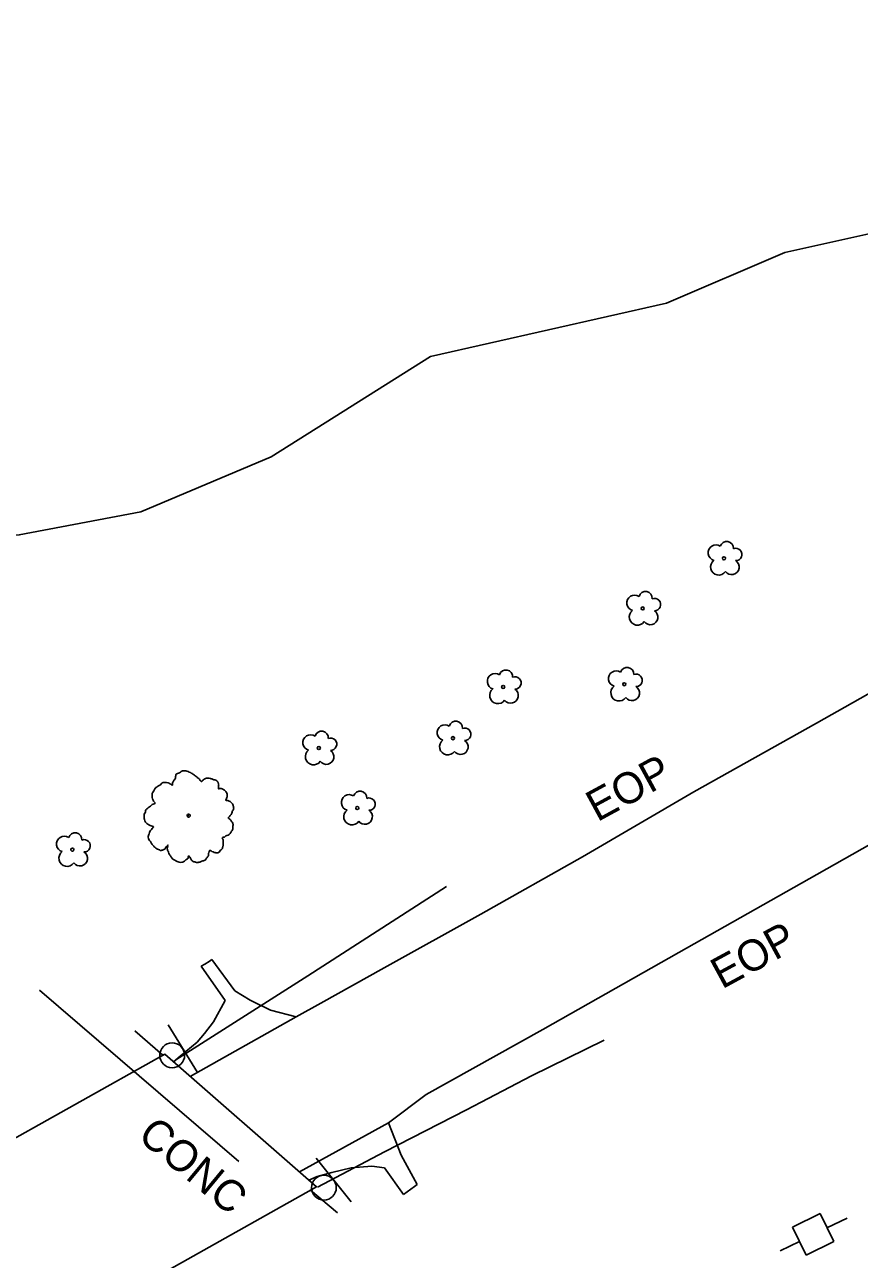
# Model space of a CAD drawing. Extents: x 2076109 to 2080761, y 592812 to 596750.
# Drawn here: x 2077392.1 to 2077526.3, y 595822.6 to 596021.2 of the extents above; entities that cross this region are included whole.
import ezdxf

# ---------------------------------------------------------------- set-up
doc = ezdxf.new("R2010")
doc.units = 0
for name, color, linetype in [('Default', 7, 'Continuous'), ('RD_EX_BldgApp', 7, 'Continuous'), ('RD_EX_Bridge', 7, 'Continuous'), ('RD_EX_Bridge_txCode', 7, 'Continuous'), ('RD_EX_Conc', 7, 'Continuous'), ('RD_EX_GuardRail', 7, 'Continuous'), ('RD_EX_Road', 7, 'Continuous'), ('RD_EX_Road_txCode', 7, 'Continuous'), ('RD_EX_UT', 7, 'Continuous'), ('RD_EX_VEG', 7, 'Continuous'), ('RD_Sketch1', 7, 'Continuous')]:
    doc.layers.add(name, color=color, linetype=linetype)

msp = doc.modelspace()

# ---------------------------------------------------------------- linework, layer by layer
at = {"layer": 'Default'}
msp.add_arc((2035586.7, 547847.96), 63546.51, 48.5011873, 49.2923126, dxfattribs=at)
msp.add_arc((2035586.7, 547847.96), 63546.51, 48.5011873, 49.2923126, dxfattribs=at)
at = {"layer": 'RD_EX_BldgApp'}
for p, q in [((2077419.87, 595852.63), (2077415.15, 595860.29)), ((2077419.87, 595852.63), (2077415.15, 595860.29)), ((2077444.58, 595831.87), (2077438.95, 595838.88)), ((2077444.58, 595831.87), (2077438.95, 595838.88))]:
    msp.add_line(p, q, dxfattribs=at)
for centre in [(2077415.78, 595855.41), (2077415.78, 595855.41), (2077440.18, 595834.12), (2077440.18, 595834.12)]:
    msp.add_circle(centre, 2, dxfattribs=at)
at = {"layer": 'RD_EX_Bridge'}
for p, q in [((2077409.76, 595859.33), (2077414.27, 595855.42)), ((2077409.76, 595859.33), (2077414.27, 595855.42)), ((2077442.36, 595830.09), (2077438.01, 595833.71)), ((2077442.36, 595830.09), (2077438.01, 595833.71))]:
    msp.add_line(p, q, dxfattribs=at)
msp.add_lwpolyline([(2077182.69, 595725.56), (2077226.26, 595749.95), (2077278.63, 595779.43), (2077318.69, 595801.87), (2077370.98, 595831.15), (2077414.59, 595855.59), (2077438.98, 595834.26), (2077395.4, 595809.74), (2077342.89, 595780.4), (2077302.73, 595757.84), (2077250.38, 595728.31), (2077206.95, 595704.06)], close=True, dxfattribs=at)
msp.add_lwpolyline([(2077182.69, 595725.56), (2077226.26, 595749.95), (2077278.63, 595779.43), (2077318.69, 595801.87), (2077370.98, 595831.15), (2077414.59, 595855.59), (2077438.98, 595834.26), (2077395.4, 595809.74), (2077342.89, 595780.4), (2077302.73, 595757.84), (2077250.38, 595728.31), (2077206.95, 595704.06)], close=True, dxfattribs=at)
at = {"layer": 'RD_EX_Conc'}
for p, q in [((2077424.3, 595864.22), (2077420.43, 595869.75)), ((2077424.3, 595864.22), (2077420.43, 595869.75)), ((2077449.95, 595837.32), (2077452.97, 595833.04)), ((2077449.95, 595837.32), (2077452.97, 595833.04))]:
    msp.add_line(p, q, dxfattribs=at)
for points in [[(2077420.43, 595869.75), (2077421.01, 595870.08), (2077421.72, 595870.52), (2077422.18, 595870.8)], [(2077420.43, 595869.75), (2077421.01, 595870.08), (2077421.72, 595870.52), (2077422.18, 595870.8)], [(2077422.18, 595870.8), (2077425.85, 595865.79), (2077428.32, 595864.3), (2077431.62, 595862.65), (2077435.74, 595861.59)], [(2077422.18, 595870.8), (2077425.85, 595865.79), (2077428.32, 595864.3), (2077431.62, 595862.65), (2077435.74, 595861.59)], [(2077416, 595854.36), (2077417.08, 595855.26), (2077419.78, 595857.52), (2077420.98, 595858.94), (2077422.44, 595860.78), (2077424.3, 595864.22)], [(2077416, 595854.36), (2077417.08, 595855.26), (2077419.78, 595857.52), (2077420.98, 595858.94), (2077422.44, 595860.78), (2077424.3, 595864.22)], [(2077424.3, 595864.22), (2077424.3, 595864.22)], [(2077424.3, 595864.22), (2077424.3, 595864.22)], [(2077455.21, 595834.64), (2077452.61, 595839.34), (2077450.57, 595844.56)], [(2077455.21, 595834.64), (2077452.61, 595839.34), (2077450.57, 595844.56)], [(2077437.74, 595835.34), (2077439.09, 595835.94), (2077441.48, 595836.54), (2077444.58, 595837.32), (2077447.89, 595837.59), (2077449.95, 595837.32)], [(2077437.74, 595835.34), (2077439.09, 595835.94), (2077441.48, 595836.54), (2077444.58, 595837.32), (2077447.89, 595837.59), (2077449.95, 595837.32)], [(2077452.97, 595833.04), (2077453.56, 595833.45), (2077454.77, 595834.33), (2077455.21, 595834.64)], [(2077452.97, 595833.04), (2077453.56, 595833.45), (2077454.77, 595834.33), (2077455.21, 595834.64)]]:
    msp.add_lwpolyline(points, dxfattribs=at)
at = {"layer": 'RD_EX_GuardRail'}
for points in [[(2077459.93, 595882.54), (2077437.6, 595868.21), (2077416.38, 595854.69)], [(2077459.93, 595882.54), (2077437.6, 595868.21), (2077416.38, 595854.69)], [(2077439.13, 595834.18), (2077449.93, 595839.88), (2077463.1, 595846.65), (2077473.58, 595852.13), (2077485.27, 595857.86)], [(2077439.13, 595834.18), (2077449.93, 595839.88), (2077463.1, 595846.65), (2077473.58, 595852.13), (2077485.27, 595857.86)]]:
    msp.add_lwpolyline(points, dxfattribs=at)
at = {"layer": 'RD_EX_Road'}
for points in [[(2077543.8, 595922.59), (2077519.41, 595908.81), (2077499.67, 595897.76), (2077481.77, 595887.31), (2077465.41, 595878.13), (2077449.9, 595869.47), (2077439.7, 595863.82)], [(2077543.8, 595922.59), (2077519.41, 595908.81), (2077499.67, 595897.76), (2077481.77, 595887.31), (2077465.41, 595878.13), (2077449.9, 595869.47), (2077439.7, 595863.82)], [(2077456.64, 595849.12), (2077475.41, 595859.57), (2077497.28, 595871.94), (2077518.22, 595883.81), (2077537.74, 595894.82)], [(2077456.64, 595849.12), (2077475.41, 595859.57), (2077497.28, 595871.94), (2077518.22, 595883.81), (2077537.74, 595894.82)], [(2077439.7, 595863.82), (2077435.74, 595861.59), (2077418.7, 595852)], [(2077439.7, 595863.82), (2077435.74, 595861.59), (2077418.7, 595852)], [(2077436.25, 595836.65), (2077450.57, 595844.56), (2077456.64, 595849.12)], [(2077436.25, 595836.65), (2077450.57, 595844.56), (2077456.64, 595849.12)]]:
    msp.add_lwpolyline(points, dxfattribs=at)
at = {"layer": 'RD_EX_UT'}
for p, q in [((2077520.02, 595829.97), (2077515.53, 595827.77)), ((2077520.02, 595829.97), (2077515.53, 595827.77)), ((2077522.22, 595825.48), (2077520.02, 595829.97)), ((2077522.22, 595825.48), (2077520.02, 595829.97)), ((2077521.08, 595827.64), (2077524.35, 595829.24)), ((2077521.08, 595827.64), (2077524.35, 595829.24)), ((2077515.53, 595827.77), (2077517.73, 595823.28)), ((2077515.53, 595827.77), (2077517.73, 595823.28)), ((2077513.57, 595823.96), (2077516.69, 595825.49)), ((2077513.57, 595823.96), (2077516.69, 595825.49)), ((2077517.73, 595823.28), (2077522.22, 595825.48)), ((2077517.73, 595823.28), (2077522.22, 595825.48))]:
    msp.add_line(p, q, dxfattribs=at)
at = {"layer": 'RD_EX_VEG'}
for points in [[(2077452.32, 596036.38), (2077484.3, 596038.76), (2077519.05, 596039.86), (2077543.06, 596044.55), (2077554.7, 596042.23), (2077566.69, 596033.37), (2077573.01, 596026.73), (2077575.87, 596012.73), (2077573.1, 596007.72), (2077559.2, 595996.51), (2077543.73, 595991.04), (2077514.3, 595984.51), (2077495.27, 595976.35), (2077457.35, 595967.82), (2077431.71, 595951.64)], [(2077452.32, 596036.38), (2077484.3, 596038.76), (2077519.05, 596039.86), (2077543.06, 596044.55), (2077554.7, 596042.23), (2077566.69, 596033.37), (2077573.01, 596026.73), (2077575.87, 596012.73), (2077573.1, 596007.72), (2077559.2, 595996.51), (2077543.73, 595991.04), (2077514.3, 595984.51), (2077495.27, 595976.35), (2077457.35, 595967.82), (2077431.71, 595951.64)], [(2077431.71, 595951.64), (2077410.74, 595942.79), (2077391.2, 595939.11), (2077374.98, 595938.69), (2077362.23, 595941.05), (2077351, 595938.05), (2077345.02, 595933.18), (2077341.51, 595928.41), (2077336.03, 595916.1), (2077330.47, 595912.16), (2077323.87, 595911.13), (2077317.15, 595914.07), (2077296.95, 595933.28), (2077273.45, 595955.1)], [(2077431.71, 595951.64), (2077410.74, 595942.79), (2077391.2, 595939.11), (2077374.98, 595938.69), (2077362.23, 595941.05), (2077351, 595938.05), (2077345.02, 595933.18), (2077341.51, 595928.41), (2077336.03, 595916.1), (2077330.47, 595912.16), (2077323.87, 595911.13), (2077317.15, 595914.07), (2077296.95, 595933.28), (2077273.45, 595955.1)]]:
    msp.add_lwpolyline(points, dxfattribs=at)
for centre, radius in [((2077504.53, 595935.34), 0.25), ((2077504.53, 595935.34), 0.25), ((2077491.46, 595927.28), 0.25), ((2077491.46, 595927.28), 0.25), ((2077469.02, 595914.66), 0.25), ((2077469.02, 595914.66), 0.25), ((2077488.49, 595915.09), 0.25), ((2077488.49, 595915.09), 0.25), ((2077460.94, 595906.42), 0.25), ((2077460.94, 595906.42), 0.25), ((2077439.37, 595904.82), 0.25), ((2077439.37, 595904.82), 0.25), ((2077418.43, 595893.96), 0.25), ((2077418.43, 595893.96), 0.25), ((2077418.41, 595893.95), 0.0001), ((2077418.41, 595893.95), 0.0001), ((2077445.55, 595895.18), 0.25), ((2077445.55, 595895.18), 0.25), ((2077399.73, 595888.49), 0.25), ((2077399.73, 595888.49), 0.25)]:
    msp.add_circle(centre, radius, dxfattribs=at)
for centre, radius, start, end in [((2077504.98, 595936.98), 1.08, 354.7355, 164.5153), ((2077504.98, 595936.98), 1.08, 354.7355, 164.5153), ((2077503.24, 595936.23), 1.26, 56.211, 254.4932), ((2077503.24, 595936.23), 1.26, 56.211, 254.4932), ((2077506.43, 595935.96), 0.995, 268.5218, 111.806), ((2077506.43, 595935.96), 0.995, 268.5218, 111.806), ((2077503.69, 595933.96), 1.32, 126.6419, 325.5182), ((2077503.69, 595933.96), 1.32, 126.6419, 325.5182), ((2077505.75, 595933.94), 1.22, 216.3259, 57.8639), ((2077505.75, 595933.94), 1.22, 216.3259, 57.8639), ((2077491.91, 595928.93), 1.08, 354.7355, 164.5153), ((2077491.91, 595928.93), 1.08, 354.7355, 164.5153), ((2077490.17, 595928.17), 1.26, 56.211, 254.4932), ((2077490.17, 595928.17), 1.26, 56.211, 254.4932), ((2077493.36, 595927.9), 0.995, 268.5218, 111.806), ((2077493.36, 595927.9), 0.995, 268.5218, 111.806), ((2077490.62, 595925.9), 1.32, 126.6419, 325.5182), ((2077490.62, 595925.9), 1.32, 126.6419, 325.5182), ((2077492.69, 595925.88), 1.22, 216.3259, 57.8639), ((2077492.69, 595925.88), 1.22, 216.3259, 57.8639), ((2077488.94, 595916.73), 1.08, 354.7355, 164.5153), ((2077488.94, 595916.73), 1.08, 354.7355, 164.5153), ((2077467.72, 595915.55), 1.26, 56.211, 254.4932), ((2077467.72, 595915.55), 1.26, 56.211, 254.4932), ((2077469.46, 595916.31), 1.08, 354.7355, 164.5153), ((2077469.46, 595916.31), 1.08, 354.7355, 164.5153), ((2077470.91, 595915.28), 0.995, 268.5218, 111.806), ((2077470.91, 595915.28), 0.995, 268.5218, 111.806), ((2077487.2, 595915.98), 1.26, 56.211, 254.4932), ((2077487.2, 595915.98), 1.26, 56.211, 254.4932), ((2077490.39, 595915.71), 0.995, 268.5218, 111.806), ((2077490.39, 595915.71), 0.995, 268.5218, 111.806), ((2077468.17, 595913.28), 1.32, 126.6419, 325.5182), ((2077468.17, 595913.28), 1.32, 126.6419, 325.5182), ((2077470.24, 595913.26), 1.22, 216.3259, 57.8639), ((2077470.24, 595913.26), 1.22, 216.3259, 57.8639), ((2077487.65, 595913.71), 1.32, 126.6419, 325.5182), ((2077487.65, 595913.71), 1.32, 126.6419, 325.5182), ((2077489.72, 595913.68), 1.22, 216.3259, 57.8639), ((2077489.72, 595913.68), 1.22, 216.3259, 57.8639), ((2077459.65, 595907.31), 1.26, 56.211, 254.4932), ((2077459.65, 595907.31), 1.26, 56.211, 254.4932), ((2077461.39, 595908.07), 1.08, 354.7355, 164.5153), ((2077461.39, 595908.07), 1.08, 354.7355, 164.5153), ((2077462.84, 595907.04), 0.995, 268.5218, 111.806), ((2077462.84, 595907.04), 0.995, 268.5218, 111.806), ((2077438.07, 595905.71), 1.26, 56.211, 254.4932), ((2077438.07, 595905.71), 1.26, 56.211, 254.4932), ((2077439.82, 595906.47), 1.08, 354.7355, 164.5153), ((2077439.82, 595906.47), 1.08, 354.7355, 164.5153), ((2077441.27, 595905.45), 0.995, 268.5218, 111.806), ((2077441.27, 595905.45), 0.995, 268.5218, 111.806), ((2077460.1, 595905.04), 1.32, 126.6419, 325.5182), ((2077460.1, 595905.04), 1.32, 126.6419, 325.5182), ((2077462.16, 595905.02), 1.22, 216.3259, 57.8639), ((2077462.16, 595905.02), 1.22, 216.3259, 57.8639), ((2077438.52, 595903.45), 1.32, 126.6419, 325.5182), ((2077438.52, 595903.45), 1.32, 126.6419, 325.5182), ((2077440.59, 595903.42), 1.22, 216.3259, 57.8639), ((2077440.59, 595903.42), 1.22, 216.3259, 57.8639), ((2077446, 595896.83), 1.08, 354.7355, 164.5153), ((2077446, 595896.83), 1.08, 354.7355, 164.5153), ((2077444.25, 595896.07), 1.26, 56.211, 254.4932), ((2077444.25, 595896.07), 1.26, 56.211, 254.4932), ((2077447.44, 595895.81), 0.995, 268.5218, 111.806), ((2077447.44, 595895.81), 0.995, 268.5218, 111.806), ((2077444.7, 595893.8), 1.32, 126.6419, 325.5182), ((2077444.7, 595893.8), 1.32, 126.6419, 325.5182), ((2077446.77, 595893.78), 1.22, 216.3259, 57.8639), ((2077446.77, 595893.78), 1.22, 216.3259, 57.8639), ((2077398.44, 595889.38), 1.26, 56.0792, 254.3614), ((2077398.44, 595889.38), 1.26, 56.0792, 254.3614), ((2077400.18, 595890.13), 1.08, 354.6037, 164.3834), ((2077400.18, 595890.13), 1.08, 354.6037, 164.3834), ((2077401.63, 595889.11), 0.995, 268.39, 111.6741), ((2077401.63, 595889.11), 0.995, 268.39, 111.6741), ((2077398.88, 595887.11), 1.32, 126.51, 325.3863), ((2077398.88, 595887.11), 1.32, 126.51, 325.3863), ((2077400.95, 595887.08), 1.22, 216.1941, 57.732), ((2077400.95, 595887.08), 1.22, 216.1941, 57.732)]:
    msp.add_arc(centre, radius, start, end, dxfattribs=at)
for points in [[(2077423.16, 595899.34), (2077422.95, 595899.56), (2077422.64, 595899.69), (2077422.38, 595899.77), (2077422.16, 595899.86), (2077421.93, 595899.93), (2077421.58, 595899.99), (2077421.28, 595899.98), (2077421.03, 595899.87), (2077420.84, 595899.73), (2077420.63, 595899.56), (2077420.51, 595899.42), (2077420.4, 595899.49), (2077420.3, 595899.6), (2077420.16, 595899.82), (2077419.97, 595899.98), (2077419.78, 595900.14), (2077419.5, 595900.35), (2077419.23, 595900.58), (2077418.99, 595900.72), (2077418.71, 595900.89), (2077418.34, 595901.03), (2077417.99, 595901.16), (2077417.6, 595901.17), (2077417.11, 595900.97), (2077416.78, 595900.78), (2077416.51, 595900.69), (2077416.33, 595900.25), (2077416.24, 595899.87), (2077416.13, 595899.7), (2077415.91, 595899.32), (2077415.84, 595899.09), (2077415.81, 595898.85), (2077415.74, 595898.88), (2077415.42, 595899.09), (2077415.12, 595899.21), (2077414.65, 595899.31), (2077414.34, 595899.28), (2077414.05, 595899.1), (2077413.81, 595898.85), (2077413.6, 595898.76), (2077413.37, 595898.6), (2077413.3, 595898.56), (2077413.05, 595898.34), (2077412.84, 595897.93), (2077412.63, 595897.65), (2077412.58, 595897.4), (2077412.58, 595897.17), (2077412.55, 595896.86), (2077412.71, 595896.43), (2077412.9, 595896.15), (2077413.03, 595896), (2077412.58, 595895.73), (2077412.31, 595895.5), (2077411.96, 595895.27), (2077411.91, 595895.21), (2077411.57, 595894.88), (2077411.47, 595894.54), (2077411.28, 595894.21), (2077411.27, 595893.92), (2077411.29, 595893.51), (2077411.39, 595893.13), (2077411.69, 595892.71), (2077412.01, 595892.47), (2077412.57, 595892.24), (2077412.8, 595892.13), (2077412.67, 595892.02), (2077412.45, 595891.71), (2077412.18, 595891.39), (2077412.08, 595891.04), (2077411.98, 595890.77), (2077411.93, 595890.48), (2077412.03, 595890.1), (2077412.29, 595889.79), (2077412.52, 595889.4), (2077412.81, 595889.05), (2077413.18, 595888.71), (2077413.73, 595888.43), (2077414.02, 595888.35), (2077414.21, 595888.42), (2077414.61, 595888.58), (2077414.72, 595888.78), (2077415.12, 595889.22), (2077415.08, 595889.02), (2077414.99, 595888.64), (2077415.18, 595888.09), (2077415.37, 595887.7), (2077415.64, 595887.28), (2077415.82, 595887.03), (2077416.23, 595886.78), (2077416.56, 595886.59), (2077416.93, 595886.45), (2077417.34, 595886.46), (2077417.65, 595886.56), (2077417.86, 595886.74), (2077418.16, 595886.98), (2077418.31, 595887.08)], [(2077423.16, 595899.34), (2077422.95, 595899.56), (2077422.64, 595899.69), (2077422.38, 595899.77), (2077422.16, 595899.86), (2077421.93, 595899.93), (2077421.58, 595899.99), (2077421.28, 595899.98), (2077421.03, 595899.87), (2077420.84, 595899.73), (2077420.63, 595899.56), (2077420.51, 595899.42), (2077420.4, 595899.49), (2077420.3, 595899.6), (2077420.16, 595899.82), (2077419.97, 595899.98), (2077419.78, 595900.14), (2077419.5, 595900.35), (2077419.23, 595900.58), (2077418.99, 595900.72), (2077418.71, 595900.89), (2077418.34, 595901.03), (2077417.99, 595901.16), (2077417.6, 595901.17), (2077417.11, 595900.97), (2077416.78, 595900.78), (2077416.51, 595900.69), (2077416.33, 595900.25), (2077416.24, 595899.87), (2077416.13, 595899.7), (2077415.91, 595899.32), (2077415.84, 595899.09), (2077415.81, 595898.85), (2077415.74, 595898.88), (2077415.42, 595899.09), (2077415.12, 595899.21), (2077414.65, 595899.31), (2077414.34, 595899.28), (2077414.05, 595899.1), (2077413.81, 595898.85), (2077413.6, 595898.76), (2077413.37, 595898.6), (2077413.3, 595898.56), (2077413.05, 595898.34), (2077412.84, 595897.93), (2077412.63, 595897.65), (2077412.58, 595897.4), (2077412.58, 595897.17), (2077412.55, 595896.86), (2077412.71, 595896.43), (2077412.9, 595896.15), (2077413.03, 595896), (2077412.58, 595895.73), (2077412.31, 595895.5), (2077411.96, 595895.27), (2077411.91, 595895.21), (2077411.57, 595894.88), (2077411.47, 595894.54), (2077411.28, 595894.21), (2077411.27, 595893.92), (2077411.29, 595893.51), (2077411.39, 595893.13), (2077411.69, 595892.71), (2077412.01, 595892.47), (2077412.57, 595892.24), (2077412.8, 595892.13), (2077412.67, 595892.02), (2077412.45, 595891.71), (2077412.18, 595891.39), (2077412.08, 595891.04), (2077411.98, 595890.77), (2077411.93, 595890.48), (2077412.03, 595890.1), (2077412.29, 595889.79), (2077412.52, 595889.4), (2077412.81, 595889.05), (2077413.18, 595888.71), (2077413.73, 595888.43), (2077414.02, 595888.35), (2077414.21, 595888.42), (2077414.61, 595888.58), (2077414.72, 595888.78), (2077415.12, 595889.22), (2077415.08, 595889.02), (2077414.99, 595888.64), (2077415.18, 595888.09), (2077415.37, 595887.7), (2077415.64, 595887.28), (2077415.82, 595887.03), (2077416.23, 595886.78), (2077416.56, 595886.59), (2077416.93, 595886.45), (2077417.34, 595886.46), (2077417.65, 595886.56), (2077417.86, 595886.74), (2077418.16, 595886.98), (2077418.31, 595887.08)], [(2077418.31, 595887.08), (2077418.37, 595887.26), (2077418.49, 595887.48), (2077418.53, 595887.41), (2077418.64, 595887.26), (2077418.77, 595886.99), (2077418.89, 595886.79), (2077419.15, 595886.6), (2077419.43, 595886.5), (2077419.95, 595886.42), (2077420.46, 595886.6), (2077420.93, 595886.73), (2077421.2, 595886.93), (2077421.31, 595887.13), (2077421.61, 595887.53), (2077421.62, 595887.85), (2077421.66, 595887.98), (2077421.84, 595888.35), (2077421.93, 595888.34), (2077422.18, 595888.2), (2077422.54, 595888.05), (2077422.83, 595887.97), (2077423.12, 595887.96), (2077423.32, 595888.08), (2077423.56, 595888.4), (2077423.86, 595888.67), (2077423.9, 595888.84), (2077423.92, 595889.02), (2077423.99, 595889.22), (2077423.97, 595889.43), (2077423.99, 595889.61), (2077423.98, 595889.75), (2077423.98, 595889.94), (2077423.93, 595890.15), (2077423.85, 595890.29), (2077423.9, 595890.43), (2077424.15, 595890.49), (2077424.25, 595890.53), (2077424.41, 595890.69), (2077424.81, 595890.81), (2077425.11, 595891.08), (2077425.35, 595891.44), (2077425.48, 595891.68), (2077425.55, 595891.99), (2077425.56, 595892.31), (2077425.57, 595892.52), (2077425.52, 595892.73), (2077425.35, 595893.04), (2077425.2, 595893.24), (2077424.93, 595893.46), (2077424.81, 595893.63), (2077424.86, 595893.65), (2077424.96, 595893.77), (2077425.13, 595893.98), (2077425.37, 595894.37), (2077425.58, 595894.85), (2077425.59, 595894.86), (2077425.68, 595895.12), (2077425.63, 595895.42), (2077425.57, 595895.61), (2077425.49, 595895.83), (2077425.32, 595896.01), (2077425.09, 595896.21), (2077424.85, 595896.34), (2077424.63, 595896.4), (2077424.42, 595896.42), (2077424.46, 595896.58), (2077424.57, 595896.87), (2077424.63, 595897.02), (2077424.63, 595897.25), (2077424.59, 595897.55), (2077424.33, 595897.93), (2077423.8, 595898.28), (2077423.44, 595898.32), (2077423.22, 595898.28), (2077423.26, 595898.41), (2077423.23, 595898.69), (2077423.27, 595898.89), (2077423.22, 595899.1), (2077423.17, 595899.27), (2077423.12, 595899.38)], [(2077418.31, 595887.08), (2077418.37, 595887.26), (2077418.49, 595887.48), (2077418.53, 595887.41), (2077418.64, 595887.26), (2077418.77, 595886.99), (2077418.89, 595886.79), (2077419.15, 595886.6), (2077419.43, 595886.5), (2077419.95, 595886.42), (2077420.46, 595886.6), (2077420.93, 595886.73), (2077421.2, 595886.93), (2077421.31, 595887.13), (2077421.61, 595887.53), (2077421.62, 595887.85), (2077421.66, 595887.98), (2077421.84, 595888.35), (2077421.93, 595888.34), (2077422.18, 595888.2), (2077422.54, 595888.05), (2077422.83, 595887.97), (2077423.12, 595887.96), (2077423.32, 595888.08), (2077423.56, 595888.4), (2077423.86, 595888.67), (2077423.9, 595888.84), (2077423.92, 595889.02), (2077423.99, 595889.22), (2077423.97, 595889.43), (2077423.99, 595889.61), (2077423.98, 595889.75), (2077423.98, 595889.94), (2077423.93, 595890.15), (2077423.85, 595890.29), (2077423.9, 595890.43), (2077424.15, 595890.49), (2077424.25, 595890.53), (2077424.41, 595890.69), (2077424.81, 595890.81), (2077425.11, 595891.08), (2077425.35, 595891.44), (2077425.48, 595891.68), (2077425.55, 595891.99), (2077425.56, 595892.31), (2077425.57, 595892.52), (2077425.52, 595892.73), (2077425.35, 595893.04), (2077425.2, 595893.24), (2077424.93, 595893.46), (2077424.81, 595893.63), (2077424.86, 595893.65), (2077424.96, 595893.77), (2077425.13, 595893.98), (2077425.37, 595894.37), (2077425.58, 595894.85), (2077425.59, 595894.86), (2077425.68, 595895.12), (2077425.63, 595895.42), (2077425.57, 595895.61), (2077425.49, 595895.83), (2077425.32, 595896.01), (2077425.09, 595896.21), (2077424.85, 595896.34), (2077424.63, 595896.4), (2077424.42, 595896.42), (2077424.46, 595896.58), (2077424.57, 595896.87), (2077424.63, 595897.02), (2077424.63, 595897.25), (2077424.59, 595897.55), (2077424.33, 595897.93), (2077423.8, 595898.28), (2077423.44, 595898.32), (2077423.22, 595898.28), (2077423.26, 595898.41), (2077423.23, 595898.69), (2077423.27, 595898.89), (2077423.22, 595899.1), (2077423.17, 595899.27), (2077423.12, 595899.38)]]:
    msp.add_spline(points, degree=3, dxfattribs=at)
at = {"layer": 'RD_Sketch1'}
msp.add_line((2077426.51, 595838.34), (2077394.47, 595865.91), dxfattribs=at)

# ---------------------------------------------------------------- texts
at = {"layer": 'RD_EX_Bridge_txCode'}
msp.add_text('CONC', height=5, rotation=320.3709, dxfattribs=at).set_placement((2077410.01, 595842.08))
msp.add_text('CONC', height=5, rotation=320.3709, dxfattribs=at).set_placement((2077410.01, 595842.08))
at = {"layer": 'RD_EX_Road_txCode'}
for p in [(2077484.15, 595892.88), (2077484.15, 595892.88), (2077504.21, 595865.98), (2077504.21, 595865.98)]:
    msp.add_text('EOP', height=5, rotation=28.5196, dxfattribs=at).set_placement(p)

doc.saveas('drawing.dxf')
